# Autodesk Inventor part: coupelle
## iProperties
Shininess: 64.0
Length Units: 11269
Angle Units: 11279
Time Units: 11290
Mass Units: 11283
Length Display Precision: 3
Angle Display Precision: 2
Compacted: True
Part Number: coupelle
Document SubType Name: Modeling
Created: 2005-01
Material: Par défaut
Designer: LEGERET Philippe
Density: 0.0
Volumn: 0.0
Area: 0.0
PropertySet Name: Model Information
Control State: 0
Master: False
Checked Out: False
Author: LEGERET Philippe
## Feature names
1. Extrusion1
2. Extrusion2
3. Chanfrein1 [Chamfer]
4. Perçage1 [Hole]
5. Chanfrein2 [Chamfer]
